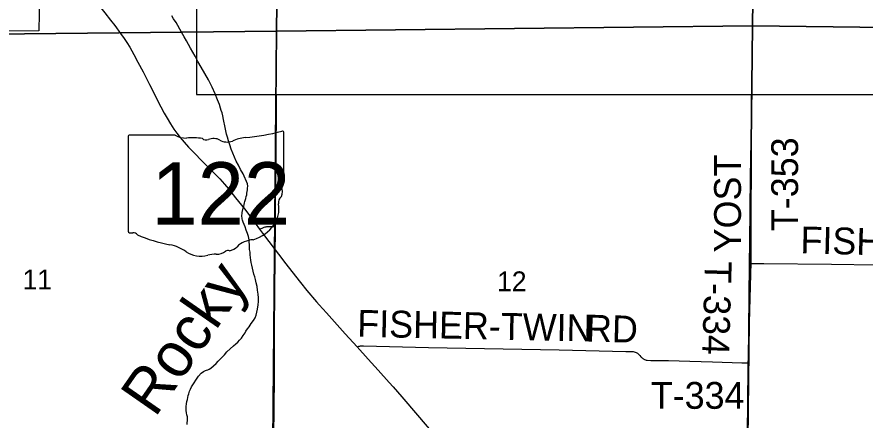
# Model space of a CAD drawing. Extents: x 0 to 34, y 0 to 22.
# Drawn here: x 26.301 to 27.199, y 17.43 to 17.857 of the extents above; entities that cross this region are included whole.
import ezdxf

# ---------------------------------------------------------------- set-up
doc = ezdxf.new("R2010")
doc.units = 0
for name, color, linetype in [('GM_X_Corporation', 7, 'Continuous'), ('GM_X_County_Road', 7, 'Continuous'), ('GM_X_Minor_River', 7, 'Continuous'), ('GM_X_Minor_River_Text', 7, 'Continuous'), ('GM_X_Section', 7, 'Continuous'), ('GM_X_Section_Text', 7, 'Continuous'), ('GM_X_State_Location', 7, 'Continuous'), ('GM_X_State_Route', 7, 'Continuous'), ('GM_X_State_Shield', 7, 'Continuous'), ('GM_X_Township', 7, 'Continuous'), ('GM_X_Township_Road', 7, 'Continuous'), ('GM_X_Township_Road_Text', 7, 'Continuous'), ('SC_Scratch1', 7, 'Continuous'), ('SH_Text', 7, 'Continuous')]:
    doc.layers.add(name, color=color, linetype=linetype)

msp = doc.modelspace()

# ---------------------------------------------------------------- linework, layer by layer
at = {"layer": 'GM_X_Corporation'}
msp.add_lwpolyline([(26.32645, 17.93423), (26.32468, 17.84219), (26.22518, 17.84182)], dxfattribs=at)
at = {"layer": 'GM_X_County_Road'}
for points in [[(26.57583, 17.71426), (26.57592, 17.72206), (26.5762, 17.75065), (26.57631, 17.77147), (26.57635, 17.77484)], [(26.57272, 17.35387), (26.57339, 17.40271), (26.57386, 17.45333), (26.57398, 17.46513), (26.57416, 17.53315), (26.57444, 17.55862), (26.57494, 17.61026), (26.57512, 17.62649), (26.57502, 17.6352), (26.57513, 17.64685), (26.57517, 17.66177), (26.57545, 17.68663), (26.57577, 17.70988), (26.57583, 17.71426)], [(26.5584, 17.6321), (26.56103, 17.63337), (26.5619, 17.6338), (26.56302, 17.6343), (26.56407, 17.63462), (26.56521, 17.6348), (26.56617, 17.63489), (26.56862, 17.63507), (26.5729, 17.63516), (26.57502, 17.6352)]]:
    msp.add_lwpolyline(points, dxfattribs=at)
at = {"layer": 'GM_X_Minor_River'}
for points in [[(26.5226, 17.73618), (26.52178, 17.73982), (26.52018, 17.74825), (26.51937, 17.75209), (26.51854, 17.75535), (26.51767, 17.75767), (26.51682, 17.76036), (26.51581, 17.76402), (26.51391, 17.76922), (26.51129, 17.7756), (26.50812, 17.78256), (26.50441, 17.79012), (26.50029, 17.79711), (26.49636, 17.80373), (26.49297, 17.80975), (26.49012, 17.81518), (26.48763, 17.81965), (26.48531, 17.82373), (26.48317, 17.82761), (26.48084, 17.8315), (26.47835, 17.83596), (26.47567, 17.84082), (26.46996, 17.85092), (26.46727, 17.85501), (26.46528, 17.85794)], [(26.48128, 17.44975), (26.48193, 17.45201), (26.48283, 17.45616), (26.48347, 17.45804), (26.48413, 17.46068), (26.48515, 17.46293), (26.48638, 17.46536), (26.4936, 17.47671), (26.49655, 17.47984), (26.49888, 17.48146), (26.50024, 17.48237), (26.5012, 17.48271), (26.50215, 17.48287), (26.50368, 17.48319), (26.50503, 17.48391), (26.50677, 17.48499), (26.51226, 17.49012), (26.51462, 17.49251), (26.51639, 17.49434), (26.5211, 17.49912), (26.52368, 17.50226), (26.52702, 17.50557), (26.53054, 17.50887), (26.53326, 17.51086), (26.53522, 17.51269), (26.53719, 17.51472), (26.53935, 17.51692), (26.54077, 17.51954), (26.54216, 17.5212), (26.54296, 17.5225), (26.54378, 17.52437), (26.54538, 17.5266), (26.54717, 17.52901), (26.54956, 17.53254), (26.55176, 17.5357), (26.55356, 17.53829), (26.55461, 17.5413), (26.55529, 17.54432), (26.55597, 17.54753), (26.55669, 17.55207), (26.5572, 17.55567), (26.55714, 17.55948), (26.55672, 17.56349), (26.55629, 17.56769), (26.55568, 17.57171), (26.55468, 17.57555), (26.55385, 17.57901), (26.55319, 17.58189), (26.55235, 17.58477), (26.55169, 17.58765), (26.55086, 17.5911), (26.55021, 17.59417), (26.54955, 17.59686), (26.54908, 17.59954), (26.54861, 17.60241), (26.54832, 17.60509), (26.54823, 17.60795), (26.54776, 17.61082), (26.54768, 17.61386), (26.54757, 17.61615), (26.54728, 17.61864), (26.54718, 17.62111), (26.54672, 17.62437), (26.54551, 17.62764), (26.54412, 17.63112), (26.5431, 17.63458), (26.54206, 17.63728), (26.54101, 17.6398), (26.54033, 17.64191), (26.54, 17.64326), (26.53984, 17.64421), (26.5397, 17.64555), (26.53985, 17.64992), (26.54072, 17.65294), (26.54096, 17.65445), (26.54158, 17.65614), (26.54185, 17.65841), (26.54229, 17.66011), (26.54272, 17.66143), (26.54314, 17.66255), (26.54379, 17.66481), (26.54424, 17.66689), (26.54467, 17.6684), (26.54474, 17.6703), (26.54517, 17.672), (26.54542, 17.6737), (26.54569, 17.67578), (26.54576, 17.67787), (26.54546, 17.68017), (26.5411, 17.69079), (26.53823, 17.69546), (26.53593, 17.70011), (26.53361, 17.70419), (26.53167, 17.70845), (26.52993, 17.7127), (26.52817, 17.71676), (26.52682, 17.72137), (26.52545, 17.72561), (26.52426, 17.72946), (26.52343, 17.73272), (26.5226, 17.73618)], [(26.48175, 17.42537), (26.48197, 17.43164), (26.48185, 17.43355), (26.48135, 17.43566), (26.48087, 17.43796), (26.48076, 17.44044), (26.48064, 17.44235), (26.48072, 17.44463), (26.481, 17.44728), (26.48128, 17.44975)]]:
    msp.add_lwpolyline(points, dxfattribs=at)
at = {"layer": 'GM_X_Section'}
for points in [[(26.0861, 18.36703), (26.57728, 18.35319), (26.58276, 18.35287), (26.57637, 17.84179), (26.07549, 17.83653)], [(26.58276, 18.35287), (27.08683, 18.34626), (27.08014, 17.8475), (26.57637, 17.84179)], [(27.08683, 18.34626), (27.56534, 18.3408), (27.57008, 18.34069), (27.56357, 17.84155), (27.08014, 17.8475)], [(27.08014, 17.8475), (27.07455, 17.34645), (27.07407, 17.31729), (26.57181, 17.32802), (26.57637, 17.84179)], [(27.56357, 17.84155), (27.55806, 17.33595), (27.07455, 17.34645), (27.08014, 17.8475)], [(26.57637, 17.84179), (26.57181, 17.32802), (26.0699, 17.33338), (26.07549, 17.83653)]]:
    msp.add_lwpolyline(points, close=True, dxfattribs=at)
at = {"layer": 'GM_X_State_Route'}
for points in [[(26.33486, 17.93781), (26.3401, 17.9313), (26.34573, 17.92426), (26.35517, 17.9119), (26.36315, 17.90158), (26.37022, 17.89252), (26.37801, 17.88243), (26.38752, 17.87015), (26.39443, 17.86136), (26.40058, 17.85354), (26.40511, 17.84761), (26.41116, 17.83931), (26.4149, 17.83395), (26.41763, 17.82978), (26.42076, 17.82476), (26.42515, 17.81723), (26.42957, 17.80901), (26.43489, 17.79881), (26.44163, 17.7855), (26.44947, 17.77009)], [(26.44947, 17.77009), (26.45036, 17.76833), (26.4573, 17.75513), (26.46033, 17.74972), (26.46403, 17.74362), (26.46759, 17.73818), (26.47065, 17.7339), (26.47425, 17.72924), (26.47842, 17.72425), (26.48318, 17.71893), (26.48853, 17.71332)], [(26.48853, 17.71332), (26.49796, 17.70386), (26.50896, 17.69289), (26.51609, 17.6855), (26.52113, 17.67998), (26.52537, 17.675), (26.53299, 17.66556), (26.54219, 17.65381), (26.54892, 17.64487), (26.5584, 17.6321), (26.56151, 17.6279), (26.57494, 17.61026), (26.57845, 17.60564), (26.58629, 17.59561), (26.59622, 17.58249), (26.60157, 17.57563), (26.60823, 17.56743), (26.61855, 17.5554), (26.62153, 17.55209)], [(26.62153, 17.55209), (26.62916, 17.54363), (26.64912, 17.52148), (26.66173, 17.5076), (26.67336, 17.4948), (26.68387, 17.48296), (26.69558, 17.47009), (26.69973, 17.46547), (26.70892, 17.45494), (26.72568, 17.43535), (26.74178, 17.41643), (26.74793, 17.40903), (26.74933, 17.40736), (26.75391, 17.40187), (26.76687, 17.38639), (26.7745, 17.37699), (26.77926, 17.37125), (26.79603, 17.35085), (26.80337, 17.3419)]]:
    msp.add_lwpolyline(points, dxfattribs=at)
at = {"layer": 'GM_X_State_Shield'}
for p, q in [((26.41922, 17.73012), (26.41922, 17.63006)), ((26.4691, 17.73184), (26.42084, 17.73184)), ((26.58401, 17.68198), (26.58401, 17.73432)), ((26.58399, 17.68199), (26.58401, 17.68198))]:
    msp.add_line(p, q, dxfattribs=at)
for centre, major_axis, start_param, end_param in [((26.4211, 17.73033), (0.00191, 0), 1.712693, 3.28349), ((26.48059, 17.74346), (0.01852, 0), 4.042523, 4.731795), ((26.48673, 17.67567), (0.06648, 0), 1.404758, 1.657858), ((26.50182, 17.73085), (0.00534, 0), 3.836095, 5.185415), ((26.50967, 17.71929), (0.01111, 0), 0.950623, 2.079405), ((26.5476, 17.70128), (0.03516, 0), 1.699011, 2.107814), ((26.52531, 17.86826), (0.17476, 0), 4.814394, 5.042369), ((26.58218, 17.73454), (0.00183, 0), 6.141152, 7.989035), ((26.524, 17.73515), (0.01336, 0), 4.081561, 5.145723), ((26.58358, 17.67814), (0.00284, 0), 1.883978, 3.671073), ((26.56552, 17.67152), (0.01704, 0), 5.934695, 6.695948), ((26.58205, 17.68178), (0.00196, 0), 5.05454, 6.418171), ((26.59058, 17.66008), (0.0124, 0), 2.387724, 3.262537), ((26.5351, 17.65342), (0.04371, 0), 5.101752, 6.440018), ((26.42112, 17.62984), (0.00193, 0), 3.00124, 4.508301), ((26.42141, 17.64008), (0.0147, 0), 4.665946, 4.897461), ((26.42442, 17.62429), (0.0053, 0), 0.519207, 1.627899), ((26.49133, 17.71419), (0.1262, 0), 4.195997, 4.488961), ((26.55353, 17.60197), (0.02394, 0), 1.647645, 2.488434), ((26.45371, 17.58511), (0.03949, 0), 0.823519, 1.323587), ((26.5232, 17.62036), (0.01412, 0), 4.937069, 5.64225), ((26.49641, 17.62379), (0.02506, 0), 4.026481, 4.996735), ((26.51089, 17.5892), (0.02059, 0), 1.495662, 1.94098), ((26.51272, 17.6163), (0.01335, 0), 4.691044, 5.507374), ((26.5248, 17.60661), (0.00376, 0), 1.147584, 2.315152)]:
    msp.add_ellipse(centre, major_axis=major_axis, ratio=0.8, start_param=start_param, end_param=end_param, dxfattribs=at)
at = {"layer": 'GM_X_Township'}
msp.add_lwpolyline([(27.07402, 17.35902), (27.07526, 17.4432), (27.07586, 17.4911), (27.07597, 17.49494), (27.07879, 17.59717), (27.07923, 17.75087), (27.0793, 17.77484)], dxfattribs=at)
at = {"layer": 'GM_X_Township_Road'}
for points in [[(27.07722, 17.59581), (27.07747, 17.61812), (27.07833, 17.68769), (27.07953, 17.76193), (27.07971, 17.77484)], [(27.07604, 17.4908), (27.07607, 17.49325), (27.07682, 17.56034), (27.07722, 17.59581)], [(27.07722, 17.59581), (27.07989, 17.59585), (27.09221, 17.59601), (27.1641, 17.5952), (27.25912, 17.59374), (27.37215, 17.59215), (27.47028, 17.59115), (27.5361, 17.59042), (27.55822, 17.59017), (27.56029, 17.59015)], [(26.66173, 17.5076), (26.66273, 17.50798), (26.66342, 17.50824), (26.66444, 17.50849), (26.66525, 17.50866), (26.66644, 17.50875), (26.6684, 17.50872), (26.73734, 17.50714), (26.81622, 17.50565), (26.87553, 17.5044), (26.93205, 17.5031), (26.94612, 17.50276), (26.95282, 17.50266), (26.9539, 17.50258), (26.95505, 17.5024), (26.9561, 17.50212), (26.95698, 17.50181), (26.95785, 17.5014), (26.95852, 17.50096), (26.95928, 17.50024), (26.96089, 17.49856), (26.96216, 17.49707), (26.9629, 17.49632), (26.96347, 17.49588), (26.96401, 17.49546), (26.96473, 17.49505), (26.96537, 17.49467), (26.96606, 17.49433), (26.96698, 17.49398), (26.9677, 17.49375), (26.96827, 17.49364), (26.9688, 17.4936), (26.97248, 17.49338), (26.99144, 17.49311), (27.01388, 17.49267), (27.03801, 17.49188), (27.06906, 17.49088), (27.07341, 17.49083), (27.07604, 17.4908)], [(27.07375, 17.32308), (27.07414, 17.35876), (27.07538, 17.44293), (27.07604, 17.4908)]]:
    msp.add_lwpolyline(points, dxfattribs=at)
at = {"layer": 'SC_Scratch1'}
msp.add_lwpolyline([(27.07402, 17.35902), (27.07526, 17.4432), (27.07586, 17.4911), (27.07597, 17.49494), (27.07879, 17.59717), (27.07923, 17.75087), (27.0793, 17.77484)], dxfattribs=at)
at = {"layer": 'SH_Text'}
msp.add_lwpolyline([(28.42481, 18.17793), (26.49145, 18.17793), (26.49145, 17.77484), (28.42481, 17.77484), (28.42481, 17.87561), (28.73475, 18.11868), (28.42481, 17.97638)], close=True, dxfattribs=at)

# ---------------------------------------------------------------- texts
at = {"layer": 'GM_X_Minor_River_Text'}
msp.add_text('Rocky', height=0.047335, rotation=55.19129, dxfattribs=at).set_placement((26.44756, 17.43189))
at = {"layer": 'GM_X_Section_Text'}
for s, p in [('11', (26.30737, 17.56852)), ('12', (26.80987, 17.56659))]:
    msp.add_text(s, height=0.020928, rotation=0.00001, dxfattribs=at).set_placement(p)
at = {"layer": 'GM_X_State_Location'}
msp.add_text('122', height=0.0000947, rotation=0.00001, dxfattribs=at).set_placement((26.46633, 17.66655))
for s in ['s', 'r']:
    msp.add_text(s, height=0.0000947, dxfattribs=at).set_placement((26.49976, 17.67344))
at = {"layer": 'GM_X_State_Shield'}
msp.add_text('122', height=0.065918, dxfattribs=at).set_placement((26.44371, 17.63712))
at = {"layer": 'GM_X_Township_Road_Text'}
for s, height, rotation, p in [('T-353', 0.028409, 90, (27.12856, 17.63016)), ('YOST', 0.028409, 90, (27.06807, 17.60766)), ('FISHER-TWIN', 0.0284091, 358.49257, (27.13079, 17.60675)), ('T-334', 0.028409, 268.31515, (27.02996, 17.59869)), ('FISHER-TWIN', 0.0284091, 358.81572, (26.66156, 17.51842)), ('RD', 0.028409, 358.51191, (26.90371, 17.51341)), ('T-334', 0.028409, 0.00001, (26.97258, 17.4421))]:
    msp.add_text(s, height=height, rotation=rotation, dxfattribs=at).set_placement(p)

doc.saveas('drawing.dxf')
